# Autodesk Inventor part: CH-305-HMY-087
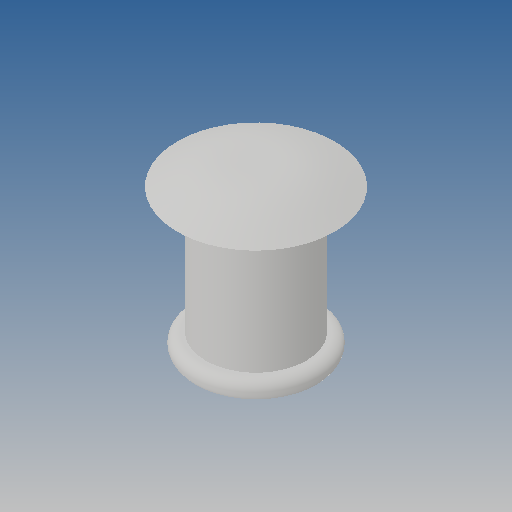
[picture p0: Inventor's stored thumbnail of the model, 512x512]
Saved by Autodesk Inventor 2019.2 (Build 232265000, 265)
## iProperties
Created: 2015-08
Part Number: CH-305-HMY-087
Material: Ogólny
Document SubType Name: Modeling
Designer: CADENGINEERING4
Density: 1 g/cm^3
Appearance: Domyślna
Author: CADENGINEERING4
Revision Number: ÈÎºÎ
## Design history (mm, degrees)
feature "Ô²½Ç1"
node "Bryła1"
